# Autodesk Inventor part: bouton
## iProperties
Shininess: 64.0
Length Units: 11269
Angle Units: 11279
Time Units: 11290
Mass Units: 11283
Length Display Precision: 3
Angle Display Precision: 2
Compacted: True
Part Number: bouton
Document SubType Name: Modeling
Created: 2003-05
Material: Par défaut
Designer: robert
Density: 1 g/cm^3
Density: 0.0
Volumn: 0.0
Area: 0.0
PropertySet Name: Model Information
Control State: 0
Master: False
Checked Out: False
Author: robert
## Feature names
1. Extrusion1
2. Extrusion2
3. Extrusion3
4. Extrusion4
5. Extrusion5
6. Révolution1 [Revolution]
7. Extrusion6
8. Extrusion7
9. Congé1 [Fillet]
